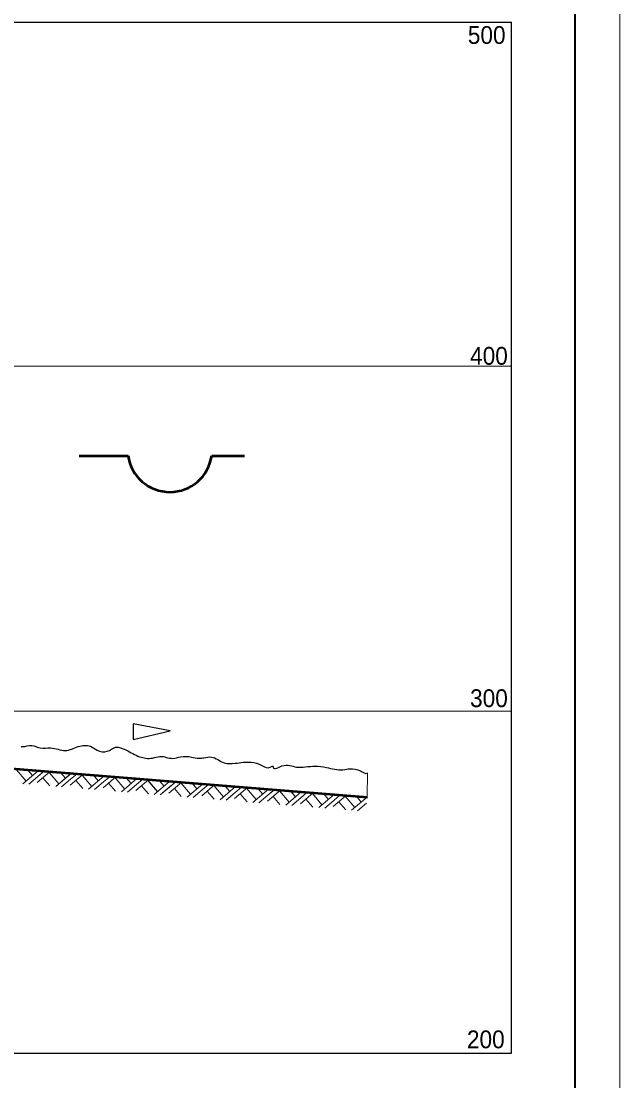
# Model space of a CAD drawing. Extents: x 8458 to 9360, y 19921 to 20366.
# Drawn here: x 9259.2 to 9360.1, y 20097.9 to 20276.6 of the extents above; entities that cross this region are included whole.
import ezdxf

# ---------------------------------------------------------------- set-up
doc = ezdxf.new("R2010")
doc.units = 0
doc.header["$LTSCALE"] = 1.2
doc.layers.add('1', color=7, linetype='Continuous', lineweight=40)
doc.layers.add('5', color=7, linetype='Continuous', lineweight=13)

msp = doc.modelspace()

# ---------------------------------------------------------------- linework, layer by layer
at = {"layer": '1'}
msp.add_line((9352.57, 19928.17), (9352.57, 20358.67), dxfattribs=at)
at = {"layer": '1', "lineweight": 13}
msp.add_lwpolyline([(8457.77, 19920.67), (9360.07, 19920.67), (9360.07, 20366.17), (8457.77, 20366.17)], close=True, dxfattribs=at)
at = {"layer": '5', "lineweight": 25}
for p, q in [((8509.89, 20276.38), (9341.84, 20276.38)), ((9341.84, 20102.58), (9341.84, 20276.38)), ((9239.91, 20152), (9317.58, 20145.74)), ((8509.89, 20102.58), (9341.84, 20102.58))]:
    msp.add_line(p, q, dxfattribs=at)
at = {"layer": '5'}
for p, q in [((8509.89, 20218.4), (9341.84, 20218.4)), ((8509.89, 20160.27), (9341.84, 20160.27)), ((9258.39, 20150.37), (9260.02, 20148.46)), ((9258.39, 20150.37), (9260.02, 20148.46)), ((9262.07, 20150.21), (9259.47, 20147.99)), ((9262.07, 20150.21), (9259.47, 20148)), ((9260.28, 20150.36), (9261.1, 20149.39)), ((9260.28, 20150.35), (9261.1, 20149.38)), ((9261.99, 20149.21), (9260.47, 20147.91)), ((9261.99, 20149.21), (9260.47, 20147.92)), ((9264.08, 20150.05), (9261.91, 20148.2)), ((9264.08, 20150.05), (9261.91, 20148.2)), ((9263.08, 20150.13), (9261.99, 20149.21)), ((9263.08, 20150.13), (9261.99, 20149.21)), ((9263.93, 20149.93), (9265.56, 20148.02)), ((9263.93, 20149.92), (9265.56, 20148.01)), ((9267.61, 20149.77), (9265.01, 20147.55)), ((9267.61, 20149.76), (9265.01, 20147.55)), ((9265.82, 20149.91), (9266.64, 20148.94)), ((9265.82, 20149.91), (9266.64, 20148.94)), ((9269.62, 20149.61), (9267.45, 20147.76)), ((9269.62, 20149.6), (9267.45, 20147.75)), ((9268.62, 20149.69), (9267.53, 20148.76)), ((9268.62, 20149.68), (9267.53, 20148.76)), ((9269.47, 20149.48), (9271.1, 20147.57)), ((9269.48, 20149.48), (9271.1, 20147.57)), ((9273.16, 20149.32), (9270.55, 20147.1)), ((9273.15, 20149.32), (9270.55, 20147.1)), ((9271.36, 20149.47), (9272.18, 20148.49)), ((9271.36, 20149.46), (9272.18, 20148.49)), ((9275.16, 20149.16), (9272.99, 20147.31)), ((9275.16, 20149.16), (9272.99, 20147.31)), ((9274.16, 20149.24), (9273.07, 20148.31)), ((9274.16, 20149.24), (9273.07, 20148.32)), ((9317.49, 20145.86), (9317.58, 20149.82)), ((9262.85, 20149), (9264.02, 20147.63)), ((9262.85, 20149), (9264.01, 20147.63)), ((9267.53, 20148.76), (9266.01, 20147.47)), ((9267.53, 20148.76), (9266.01, 20147.47)), ((9268.39, 20148.56), (9269.56, 20147.18)), ((9268.39, 20148.55), (9269.56, 20147.18)), ((9273.07, 20148.32), (9271.55, 20147.02)), ((9273.07, 20148.31), (9271.55, 20147.02)), ((9273.93, 20148.11), (9275.1, 20146.73)), ((9273.93, 20148.11), (9275.1, 20146.74)), ((9275.01, 20149.03), (9276.64, 20147.12)), ((9275.02, 20149.03), (9276.64, 20147.12)), ((9278.7, 20148.87), (9276.09, 20146.65)), ((9278.69, 20148.87), (9276.09, 20146.66)), ((9276.9, 20149.02), (9277.73, 20148.04)), ((9276.9, 20149.02), (9277.72, 20148.05)), ((9278.61, 20147.87), (9277.09, 20146.58)), ((9278.62, 20147.87), (9277.1, 20146.57)), ((9280.71, 20148.71), (9278.53, 20146.86)), ((9280.7, 20148.71), (9278.53, 20146.86)), ((9279.7, 20148.79), (9278.61, 20147.87)), ((9279.7, 20148.79), (9278.62, 20147.87)), ((9279.47, 20147.66), (9280.64, 20146.29)), ((9279.47, 20147.66), (9280.64, 20146.29)), ((9280.56, 20148.59), (9282.18, 20146.68)), ((9280.56, 20148.58), (9282.18, 20146.67)), ((9284.24, 20148.43), (9281.63, 20146.21)), ((9284.24, 20148.42), (9281.63, 20146.21)), ((9282.44, 20148.57), (9283.27, 20147.6)), ((9282.44, 20148.57), (9283.26, 20147.6)), ((9284.15, 20147.42), (9282.63, 20146.13)), ((9284.16, 20147.42), (9282.64, 20146.13)), ((9286.24, 20148.27), (9284.07, 20146.42)), ((9286.25, 20148.26), (9284.08, 20146.42)), ((9285.24, 20148.35), (9284.15, 20147.42)), ((9285.24, 20148.34), (9284.16, 20147.42)), ((9286.1, 20148.14), (9287.72, 20146.23)), ((9286.1, 20148.14), (9287.72, 20146.23)), ((9289.78, 20147.98), (9287.17, 20145.76)), ((9289.78, 20147.98), (9287.17, 20145.76)), ((9287.98, 20148.13), (9288.8, 20147.15)), ((9287.98, 20148.12), (9288.81, 20147.15)), ((9291.79, 20147.82), (9289.61, 20145.97)), ((9291.79, 20147.82), (9289.62, 20145.97)), ((9290.78, 20147.9), (9289.69, 20146.98)), ((9290.78, 20147.9), (9289.7, 20146.97)), ((9291.64, 20147.69), (9293.26, 20145.78)), ((9291.64, 20147.69), (9293.26, 20145.78)), ((9295.32, 20147.53), (9292.71, 20145.31)), ((9295.32, 20147.53), (9292.71, 20145.32)), ((9293.52, 20147.68), (9294.35, 20146.71)), ((9293.52, 20147.68), (9294.35, 20146.71)), ((9297.33, 20147.37), (9295.15, 20145.53)), ((9297.33, 20147.37), (9295.16, 20145.52)), ((9296.32, 20147.45), (9295.24, 20146.53)), ((9296.32, 20147.45), (9295.24, 20146.53)), ((9285.01, 20147.22), (9286.18, 20145.84)), ((9285.01, 20147.21), (9286.18, 20145.84)), ((9289.69, 20146.98), (9288.18, 20145.68)), ((9289.7, 20146.97), (9288.18, 20145.68)), ((9290.55, 20146.77), (9291.72, 20145.39)), ((9290.55, 20146.77), (9291.72, 20145.4)), ((9295.24, 20146.53), (9293.72, 20145.23)), ((9295.24, 20146.53), (9293.72, 20145.24)), ((9296.09, 20146.32), (9297.26, 20144.95)), ((9296.09, 20146.32), (9297.26, 20144.95)), ((9297.18, 20147.25), (9298.8, 20145.34)), ((9297.18, 20147.24), (9298.8, 20145.34)), ((9300.86, 20147.09), (9298.25, 20144.87)), ((9300.86, 20147.08), (9298.25, 20144.87)), ((9299.06, 20147.23), (9299.89, 20146.26)), ((9299.06, 20147.23), (9299.89, 20146.26)), ((9300.78, 20146.08), (9299.26, 20144.79)), ((9300.78, 20146.08), (9299.26, 20144.79)), ((9302.87, 20146.93), (9300.7, 20145.08)), ((9302.87, 20146.92), (9300.7, 20145.08)), ((9301.86, 20147.01), (9300.78, 20146.08)), ((9301.86, 20147), (9300.78, 20146.08)), ((9301.63, 20145.88), (9302.8, 20144.5)), ((9301.63, 20145.87), (9302.8, 20144.5)), ((9302.72, 20146.8), (9304.34, 20144.89)), ((9302.72, 20146.8), (9304.34, 20144.89)), ((9306.4, 20146.64), (9303.79, 20144.42)), ((9306.4, 20146.64), (9303.79, 20144.42)), ((9304.6, 20146.79), (9305.43, 20145.82)), ((9304.6, 20146.78), (9305.43, 20145.81)), ((9306.32, 20145.64), (9304.8, 20144.34)), ((9306.32, 20145.63), (9304.8, 20144.34)), ((9308.41, 20146.48), (9306.24, 20144.63)), ((9308.41, 20146.48), (9306.24, 20144.63)), ((9307.4, 20146.56), (9306.32, 20145.63)), ((9307.4, 20146.56), (9306.32, 20145.64)), ((9308.26, 20146.35), (9309.88, 20144.44)), ((9308.26, 20146.35), (9309.88, 20144.44)), ((9311.94, 20146.19), (9309.33, 20143.98)), ((9311.94, 20146.19), (9309.34, 20143.98)), ((9310.14, 20146.34), (9310.97, 20145.37)), ((9310.14, 20146.34), (9310.97, 20145.37)), ((9313.95, 20146.03), (9311.78, 20144.18)), ((9313.95, 20146.03), (9311.78, 20144.19)), ((9312.94, 20146.11), (9311.86, 20145.19)), ((9312.94, 20146.11), (9311.86, 20145.19)), ((9313.8, 20145.91), (9315.42, 20144)), ((9313.8, 20145.9), (9315.42, 20144)), ((9317.48, 20145.75), (9314.87, 20143.53)), ((9317.48, 20145.75), (9314.88, 20143.53)), ((9315.68, 20145.89), (9316.51, 20144.92)), ((9315.68, 20145.89), (9316.51, 20144.92)), ((9307.17, 20145.43), (9308.34, 20144.06)), ((9307.17, 20145.43), (9308.34, 20144.06)), ((9311.86, 20145.19), (9310.34, 20143.89)), ((9311.86, 20145.19), (9310.34, 20143.9)), ((9312.71, 20144.98), (9313.88, 20143.61)), ((9312.72, 20144.98), (9313.88, 20143.61)), ((9317.4, 20144.74), (9315.88, 20143.45)), ((9317.4, 20144.74), (9315.88, 20143.45))]:
    msp.add_line(p, q, dxfattribs=at)
at = {"layer": '5', "lineweight": 53}
for p, q in [((9268.98, 20203.31), (9277.22, 20203.31)), ((9291.32, 20203.31), (9296.82, 20203.31)), ((9239.91, 20152), (9317.58, 20145.74)), ((9239.91, 20151.99), (9317.58, 20145.73))]:
    msp.add_line(p, q, dxfattribs=at)
at = {"layer": '5', "lineweight": 25}
msp.add_lwpolyline([(9284.29, 20156.91), (9278.07, 20158.13), (9278.07, 20155.49)], close=True, dxfattribs=at)
at = {"layer": '5'}
msp.add_lwpolyline([(9225.62, 20151.96), (9225.6, 20150.63), (9226.02, 20149.36), (9226.82, 20148.3), (9227.94, 20147.56), (9229.22, 20147.23), (9230.56, 20147.33), (9231.78, 20147.86), (9232.76, 20148.77), (9233.38, 20149.94), (9233.6, 20151.26), (9233.54, 20151.96), (9240.41, 20151.96), (9317.58, 20145.74)], dxfattribs=at)
at = {"layer": '5', "lineweight": 53}
msp.add_arc((9284.26, 20204.3), 7.11, 188.0346, 351.9654, dxfattribs=at)
at = {"layer": '5', "lineweight": 25}
msp.add_spline([(9259.2, 20154.26), (9259.44, 20154.26), (9260.98, 20154.45), (9262.38, 20154.04), (9264.16, 20154.06), (9266.62, 20153.61), (9268.82, 20154.26), (9270.86, 20154.32), (9272, 20153.67), (9273.7, 20153.48), (9275.08, 20154.15), (9276.84, 20153.7), (9279.14, 20152.57), (9281.32, 20152.34), (9282.56, 20152.61), (9284.74, 20152.29), (9286.04, 20152.55), (9287.88, 20152.51), (9289.14, 20152.32), (9290, 20152.4), (9291.24, 20152.51), (9293.4, 20151.54), (9295.24, 20151.45), (9297.96, 20151.65), (9299.76, 20151.11), (9301.26, 20150.84), (9301.62, 20150.97), (9301.66, 20150.8), (9303.12, 20151), (9305.6, 20150.82), (9308.72, 20150.99), (9310.64, 20150.74), (9313.42, 20150.37), (9314.6, 20150.54), (9316.36, 20150.16), (9317.56, 20149.81), (9317.58, 20149.82)], degree=3, dxfattribs=at)
at = {"layer": '5'}
msp.add_spline([(9317.58, 20149.82), (9317.56, 20149.81), (9316.36, 20150.16), (9314.6, 20150.54), (9313.42, 20150.37), (9310.64, 20150.74), (9308.72, 20150.99), (9305.6, 20150.82), (9303.12, 20151), (9301.66, 20150.8), (9301.62, 20150.97), (9301.26, 20150.84), (9299.76, 20151.11), (9297.96, 20151.65), (9295.24, 20151.45), (9293.4, 20151.54), (9291.24, 20152.51), (9290, 20152.4), (9289.14, 20152.32), (9287.88, 20152.51), (9286.04, 20152.55), (9284.74, 20152.29), (9282.56, 20152.61), (9281.32, 20152.34), (9279.14, 20152.57), (9276.84, 20153.7), (9275.08, 20154.15), (9273.7, 20153.48), (9272, 20153.67), (9270.86, 20154.32), (9268.82, 20154.26), (9266.62, 20153.61), (9264.16, 20154.06), (9262.38, 20154.04), (9260.98, 20154.45), (9259.44, 20154.26), (9259.2, 20154.26)], degree=3, dxfattribs=at)

# ---------------------------------------------------------------- texts
at = {"layer": '5', "width": 0.95}
for s, p in [('500', (9334.46, 20272.74)), ('400', (9334.84, 20218.65)), ('300', (9334.84, 20160.93)), ('200', (9334.31, 20103.41))]:
    msp.add_text(s, height=3, dxfattribs=at).set_placement(p)

doc.saveas('drawing.dxf')
